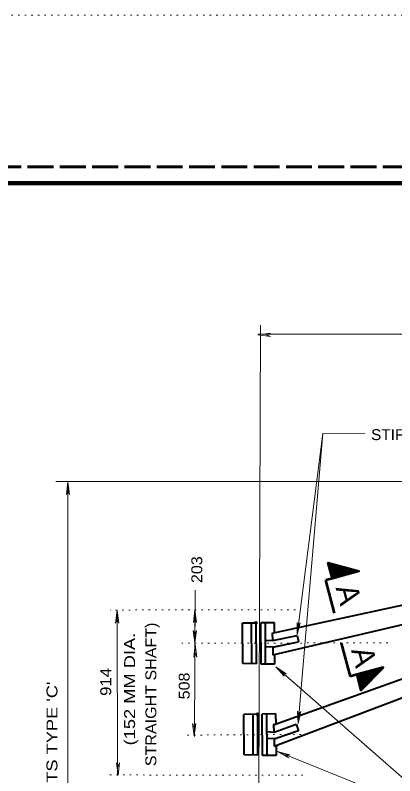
# Model space of a CAD drawing. Extents: x 312583 to 312854, y 144419 to 144597.
# Drawn here: x 312752.3 to 312778.8, y 144543.8 to 144596.8 of the extents above; entities that cross this region are included whole.
import ezdxf
from ezdxf.enums import TextEntityAlignment as Align

# ---------------------------------------------------------------- set-up
doc = ezdxf.new("R2010")
doc.units = 0
doc.header["$LTSCALE"] = 0.3
doc.header["$PDMODE"] = 32
doc.header["$PDSIZE"] = 0.15
doc.linetypes.add('DOTTED', pattern=[1.5, 0.3, -1.2])
doc.linetypes.add('LONG_DASHED', pattern=[7.5, 6, -1.5])
for name, color, linetype, lineweight in [('1', 7, 'Continuous', 35), ('2', 7, 'Continuous', 13), ('62', 7, 'DOTTED', 13), ('63', 7, 'LONG_DASHED', 60)]:
    doc.layers.add(name, color=color, linetype=linetype, lineweight=lineweight)

msp = doc.modelspace()

# ---------------------------------------------------------------- linework, layer by layer
at = {"layer": '1', "lineweight": 40}
for p, q in [((312770.2404, 144553.754), (312816.4474, 144563.7743)), ((312770.2864, 144552.259), (312811.2954, 144561.7963)), ((312770.3247, 144547.3676), (312809.233, 144561.3133)), ((312770.386, 144545.9033), (312809.325, 144560.608)), ((312769.1287, 144554.467), (312768.1704, 144554.4593)), ((312768.1857, 144551.638), (312768.1704, 144554.4593)), ((312768.822, 144551.6303), (312768.8067, 144554.467)), ((312769.144, 144551.6303), (312769.1287, 144554.467)), ((312770.4014, 144554.49), (312769.443, 144554.4746)), ((312769.4584, 144551.6073), (312769.443, 144554.4746)), ((312769.7804, 144551.6073), (312769.765, 144554.4823)), ((312770.409, 144553.7846), (312770.4014, 144554.49)), ((312770.2404, 144553.754), (312770.2557, 144553.2633)), ((312771.9807, 144553.6006), (312772.0727, 144553.156)), ((312769.7727, 144552.834), (312770.248, 144552.8186)), ((312770.271, 144552.788), (312772.0727, 144553.1636)), ((312770.271, 144552.811), (312770.2864, 144552.259)), ((312770.3554, 144552.811), (312772.0727, 144553.1636)), ((312770.409, 144552.282), (312770.409, 144551.5996)), ((312769.144, 144551.6303), (312768.1857, 144551.638)), ((312770.409, 144551.5996), (312769.4584, 144551.6073)), ((312769.2284, 144548.1113), (312768.27, 144548.1036)), ((312768.2854, 144545.2823), (312768.27, 144548.1036)), ((312768.9217, 144545.2746), (312768.9064, 144548.1113)), ((312769.2437, 144545.2746), (312769.2284, 144548.1113)), ((312770.501, 144548.1343), (312769.5427, 144548.119)), ((312769.558, 144545.2516), (312769.5427, 144548.119)), ((312769.88, 144545.2516), (312769.8647, 144548.1266)), ((312770.5087, 144547.429), (312770.501, 144548.1343)), ((312770.34, 144547.3983), (312770.6314, 144547.4596)), ((312770.34, 144547.3983), (312770.3554, 144546.8693)), ((312770.4397, 144546.417), (312772.065, 144546.992)), ((312771.9117, 144547.4213), (312772.0727, 144546.9613)), ((312769.8417, 144546.4553), (312770.4397, 144546.417)), ((312770.3707, 144546.394), (312770.386, 144545.9033)), ((312770.386, 144545.9033), (312770.6314, 144545.957)), ((312770.5087, 144545.9263), (312770.5087, 144545.244)), ((312769.2437, 144545.2746), (312768.2854, 144545.2823)), ((312770.5087, 144545.244), (312769.558, 144545.2516))]:
    msp.add_line(p, q, dxfattribs=at)
at = {"layer": '1'}
for p, q in [((312774.1427, 144558.6146), (312774.158, 144558.6376)), ((312774.158, 144558.5686), (312774.181, 144558.6376)), ((312774.1734, 144558.5226), (312774.1964, 144558.6223)), ((312774.181, 144558.4766), (312774.227, 144558.6146)), ((312774.1964, 144558.423), (312774.25, 144558.6146)), ((312774.204, 144558.3846), (312774.2654, 144558.5993)), ((312774.2194, 144558.3386), (312774.296, 144558.5993)), ((312774.2347, 144558.2926), (312774.319, 144558.5916)), ((312774.2424, 144558.2466), (312774.3344, 144558.5916)), ((312774.2577, 144558.2006), (312774.365, 144558.584)), ((312774.273, 144558.147), (312774.388, 144558.5763)), ((312774.2807, 144558.1086), (312774.411, 144558.5686)), ((312774.296, 144558.0626), (312774.434, 144558.5686)), ((312774.3114, 144558.009), (312774.457, 144558.561)), ((312774.319, 144557.963), (312774.48, 144558.5533)), ((312774.3344, 144557.9246), (312774.4954, 144558.5456)), ((312774.342, 144557.871), (312774.526, 144558.538)), ((312774.3574, 144557.825), (312774.549, 144558.538)), ((312774.3727, 144557.779), (312774.5644, 144558.5226)), ((312774.3804, 144557.733), (312774.595, 144558.515)), ((312774.3957, 144557.687), (312774.618, 144558.515)), ((312774.4034, 144557.6486), (312774.6334, 144558.4996)), ((312774.4187, 144557.595), (312774.664, 144558.4996)), ((312774.4417, 144557.5796), (312774.687, 144558.492)), ((312774.4724, 144557.5873), (312774.71, 144558.492)), ((312774.4954, 144557.595), (312774.733, 144558.4843)), ((312774.5184, 144557.595), (312774.756, 144558.4766)), ((312774.549, 144557.6026), (312774.779, 144558.469)), ((312774.572, 144557.618), (312774.802, 144558.469)), ((312774.6027, 144557.6256), (312774.825, 144558.4536)), ((312774.6257, 144557.6256), (312774.848, 144558.4536)), ((312774.6564, 144557.6333), (312774.871, 144558.446)), ((312774.687, 144557.641), (312774.894, 144558.4383)), ((312774.7024, 144557.6486), (312774.917, 144558.4383)), ((312774.733, 144557.6563), (312774.94, 144558.423)), ((312774.7637, 144557.664), (312774.9707, 144558.4153)), ((312774.7867, 144557.6716), (312774.986, 144558.4153)), ((312774.8174, 144557.687), (312775.009, 144558.4076)), ((312774.848, 144557.687), (312775.032, 144558.4)), ((312774.871, 144557.6946), (312775.055, 144558.3923)), ((312774.894, 144557.6946), (312775.078, 144558.3923)), ((312774.9247, 144557.7023), (312775.1087, 144558.3846)), ((312774.9477, 144557.71), (312775.124, 144558.377)), ((312774.9784, 144557.7176), (312775.147, 144558.3693)), ((312775.0014, 144557.7253), (312775.17, 144558.3693)), ((312775.032, 144557.733), (312775.193, 144558.354)), ((312775.055, 144557.7483), (312775.2237, 144558.3616)), ((312775.0857, 144557.7483), (312775.239, 144558.3463)), ((312775.1087, 144557.756), (312775.2697, 144558.3386)), ((312775.1394, 144557.7636), (312775.2927, 144558.3386)), ((312775.1624, 144557.7713), (312775.308, 144558.3233)), ((312775.1854, 144557.779), (312775.331, 144558.3233)), ((312775.216, 144557.7866), (312775.3617, 144558.3156)), ((312775.2467, 144557.7943), (312775.377, 144558.3156)), ((312775.2697, 144557.802), (312775.4, 144558.3003)), ((312775.3004, 144557.8096), (312775.4307, 144558.3003)), ((312775.331, 144557.8173), (312775.446, 144558.2926)), ((312775.354, 144557.8173), (312775.469, 144558.2926)), ((312775.3694, 144557.825), (312775.4997, 144558.2773)), ((312775.4, 144557.8326), (312775.5227, 144558.2773)), ((312775.4307, 144557.8403), (312775.538, 144558.2696)), ((312775.4614, 144557.848), (312775.5687, 144558.262)), ((312775.4844, 144557.8556), (312775.5917, 144558.262)), ((312775.515, 144557.8633), (312775.607, 144558.2466)), ((312775.538, 144557.871), (312775.6377, 144558.239)), ((312775.5687, 144557.8786), (312775.6607, 144558.239)), ((312775.584, 144557.8863), (312775.676, 144558.2236)), ((312775.6147, 144557.894), (312775.699, 144558.2236)), ((312775.6454, 144557.9016), (312775.7297, 144558.216)), ((312775.6684, 144557.9093), (312775.745, 144558.216)), ((312775.699, 144557.917), (312775.7757, 144558.2083)), ((312775.722, 144557.917), (312775.7987, 144558.2006)), ((312775.7527, 144557.9246), (312775.8217, 144558.193)), ((312775.7834, 144557.9323), (312775.8447, 144558.193)), ((312775.7987, 144557.94), (312775.8677, 144558.1776)), ((312775.8294, 144557.9476), (312775.8907, 144558.1776)), ((312775.8524, 144557.9553), (312775.9137, 144558.17)), ((312775.883, 144557.963), (312775.9367, 144558.1623)), ((312775.9137, 144557.9706), (312775.9597, 144558.1546)), ((312775.9444, 144557.9783), (312775.9827, 144558.147)), ((312775.9674, 144557.986), (312776.0057, 144558.1393)), ((312775.998, 144557.9936), (312776.0287, 144558.1393)), ((312776.0134, 144558.0013), (312776.0517, 144558.1316)), ((312776.0364, 144558.009), (312776.0747, 144558.124)), ((312776.067, 144558.0166), (312776.0977, 144558.1163)), ((312776.0977, 144558.0243), (312776.1207, 144558.1163)), ((312776.1284, 144558.032), (312776.1437, 144558.1086)), ((312776.1514, 144558.032), (312776.1667, 144558.101)), ((312776.182, 144558.0396), (312776.1897, 144558.0933)), ((312776.205, 144558.0473), (312776.2127, 144558.0933)), ((312776.228, 144558.055), (312776.2357, 144558.078)), ((312776.2587, 144558.0626), (312776.2587, 144558.078)), ((312777.1327, 144551.1473), (312777.4394, 144550.833)), ((312777.1634, 144551.155), (312777.4624, 144550.8483)), ((312777.1864, 144551.155), (312777.4777, 144550.8636)), ((312777.217, 144551.1703), (312777.493, 144550.8866)), ((312777.24, 144551.1703), (312777.5084, 144550.902)), ((312777.2707, 144551.178), (312777.5314, 144550.9173)), ((312777.286, 144551.1856), (312777.539, 144550.9326)), ((312777.3167, 144551.1933), (312777.562, 144550.948)), ((312777.3474, 144551.201), (312777.5774, 144550.971)), ((312777.3704, 144551.2086), (312777.5927, 144550.9786)), ((312777.401, 144551.2163), (312777.6157, 144551.0016)), ((312777.424, 144551.224), (312777.631, 144551.017)), ((312777.4547, 144551.2316), (312777.6464, 144551.04)), ((312777.4854, 144551.2393), (312777.6694, 144551.0476)), ((312777.5007, 144551.247), (312777.677, 144551.0706)), ((312777.5314, 144551.2546), (312777.7, 144551.0783)), ((312777.5544, 144551.2546), (312777.7154, 144551.1013)), ((312777.585, 144551.2623), (312777.7307, 144551.1243)), ((312777.6157, 144551.27), (312777.746, 144551.132)), ((312777.6464, 144551.2853), (312777.769, 144551.155)), ((312777.6694, 144551.2853), (312777.7767, 144551.1703)), ((312777.7, 144551.293), (312777.7997, 144551.1856)), ((312777.7154, 144551.3006), (312777.815, 144551.2086)), ((312777.7384, 144551.3083), (312777.838, 144551.224)), ((312777.769, 144551.316), (312777.8457, 144551.2393)), ((312777.7997, 144551.3236), (312777.8687, 144551.2546)), ((312777.8304, 144551.3313), (312777.884, 144551.2776)), ((312777.8534, 144551.339), (312777.8994, 144551.2853)), ((312777.884, 144551.3466), (312777.9147, 144551.3083)), ((312777.907, 144551.3543), (312777.9377, 144551.3236)), ((312777.93, 144551.362), (312777.9454, 144551.339)), ((312777.9607, 144551.3696), (312777.9684, 144551.3543)), ((312776.136, 144550.856), (312776.803, 144550.189)), ((312776.1437, 144550.879), (312776.8107, 144550.212)), ((312776.1437, 144550.8023), (312776.7724, 144550.1736)), ((312776.159, 144550.764), (312776.7647, 144550.1583)), ((312776.1667, 144550.7103), (312776.7417, 144550.143)), ((312776.1744, 144550.8866), (312776.8337, 144550.2196)), ((312776.182, 144550.6643), (312776.7264, 144550.12)), ((312776.1974, 144550.8943), (312776.849, 144550.2426)), ((312776.1974, 144550.626), (312776.711, 144550.1046)), ((312776.2204, 144550.902), (312776.8644, 144550.258)), ((312776.251, 144550.9096), (312776.8797, 144550.2733)), ((312776.274, 144550.9096), (312776.9027, 144550.2886)), ((312776.3047, 144550.9173), (312776.9104, 144550.3116)), ((312776.3277, 144550.925), (312776.9334, 144550.3193)), ((312776.3584, 144550.9403), (312776.9487, 144550.3423)), ((312776.389, 144550.948), (312776.964, 144550.3576)), ((312776.412, 144550.948), (312776.9794, 144550.373)), ((312776.435, 144550.9556), (312777.0024, 144550.396)), ((312776.4657, 144550.9633), (312777.0177, 144550.419)), ((312776.4887, 144550.971), (312777.033, 144550.4266)), ((312776.5194, 144550.971), (312777.0484, 144550.4496)), ((312776.55, 144550.9863), (312777.0714, 144550.465)), ((312776.573, 144550.994), (312777.079, 144550.4803)), ((312776.596, 144551.0016), (312777.102, 144550.4956)), ((312776.6267, 144551.0093), (312777.1174, 144550.511)), ((312776.6497, 144551.017), (312777.1327, 144550.5263)), ((312776.6804, 144551.0246), (312777.148, 144550.5493)), ((312776.7034, 144551.0323), (312777.171, 144550.557)), ((312776.734, 144551.04), (312777.1864, 144550.58)), ((312776.757, 144551.04), (312777.2094, 144550.5953)), ((312776.7877, 144551.0553), (312777.2247, 144550.6106)), ((312776.8107, 144551.0553), (312777.24, 144550.6336)), ((312776.8414, 144551.063), (312777.263, 144550.649)), ((312776.8644, 144551.0706), (312777.2707, 144550.6643)), ((312776.8874, 144551.0783), (312777.2937, 144550.6796)), ((312776.918, 144551.086), (312777.309, 144550.7026)), ((312776.9487, 144551.0936), (312777.3244, 144550.7103)), ((312776.9717, 144551.1013), (312777.3397, 144550.7333)), ((312777.0024, 144551.109), (312777.3627, 144550.7486)), ((312777.033, 144551.1166), (312777.3704, 144550.764)), ((312777.056, 144551.1243), (312777.3934, 144550.7793)), ((312777.0714, 144551.132), (312777.4087, 144550.7946)), ((312777.102, 144551.1396), (312777.4317, 144550.81)), ((312776.205, 144550.58), (312776.6957, 144550.0893)), ((312776.2204, 144550.5263), (312776.6727, 144550.0663)), ((312776.2357, 144550.4803), (312776.665, 144550.051)), ((312776.2434, 144550.4343), (312776.642, 144550.0356)), ((312776.2587, 144550.3883), (312776.6344, 144550.0203)), ((312776.2664, 144550.3423), (312776.6114, 144550.005)), ((312776.2817, 144550.2963), (312776.596, 144549.982)), ((312776.297, 144550.2426), (312776.5807, 144549.9743)), ((312776.3047, 144550.2043), (312776.5577, 144549.9513)), ((312776.32, 144550.1583), (312776.5424, 144549.936)), ((312776.3277, 144550.1123), (312776.527, 144549.9206)), ((312776.343, 144550.0586), (312776.504, 144549.9053)), ((312776.3584, 144550.0203), (312776.4964, 144549.89)), ((312776.366, 144549.9743), (312776.4734, 144549.8746)), ((312776.3814, 144549.9283), (312776.458, 144549.8516)), ((312776.3967, 144549.8746), (312776.4427, 144549.8363)), ((312776.4044, 144549.8286), (312776.4274, 144549.821))]:
    msp.add_line(p, q, dxfattribs=at)
at = {"layer": '1', "lineweight": 53}
for p, q in [((312774.4264, 144557.572), (312773.9664, 144557.4493)), ((312774.5874, 144555.1416), (312773.9664, 144557.4493)), ((312775.0474, 144553.064), (312775.6684, 144550.7486)), ((312776.1284, 144550.8713), (312775.6684, 144550.7486))]:
    msp.add_line(p, q, dxfattribs=at)
at = {"layer": '1', "lineweight": 158}
msp.add_lwpolyline([(312616.5, 144423.1446), (312616.5, 144585.0846), (312849, 144585.0846)], dxfattribs=at)
at = {"layer": '1', "lineweight": 53}
for points in [[(312774.4264, 144557.572), (312774.135, 144558.6453), (312776.274, 144558.0703)], [(312776.1284, 144550.8713), (312776.412, 144549.798), (312777.976, 144551.3696)]]:
    msp.add_lwpolyline(points, close=True, dxfattribs=at)
at = {"layer": '1', "lineweight": 40}
for points in [[(312769.788, 144553.2633), (312770.2634, 144553.248), (312771.9807, 144553.6006)], [(312769.8724, 144546.9076), (312770.3707, 144546.877), (312771.9117, 144547.4213)]]:
    msp.add_lwpolyline(points, dxfattribs=at)
at = {"layer": '1'}
for p in [(312769.1134, 144554.4746), (312769.213, 144548.119)]:
    msp.add_point(p, dxfattribs=at)
at = {"layer": '2'}
for p, q in [((312769.3127, 144541.1116), (312769.4277, 144575.1976)), ((312769.2437, 144574.5306), (312770.11, 144574.638)), ((312769.2437, 144574.5306), (312770.11, 144574.4233)), ((312828.5454, 144574.5996), (312769.2667, 144574.5843)), ((312770.11, 144574.638), (312769.834, 144574.5306)), ((312770.11, 144574.4233), (312769.834, 144574.5306)), ((312773.7747, 144567.669), (312771.973, 144553.639)), ((312773.7747, 144567.669), (312772.042, 144547.4596)), ((312776.6957, 144567.692), (312773.7747, 144567.669)), ((312840.996, 144564.3416), (312755.1677, 144564.311)), ((312756.0034, 144564.2803), (312755.9037, 144563.414)), ((312755.9957, 144517.6746), (312756.0034, 144564.265)), ((312756.0034, 144564.2803), (312756.1184, 144563.414)), ((312755.9037, 144563.414), (312756.0034, 144563.69)), ((312756.1184, 144563.414), (312756.0034, 144563.69)), ((312764.8277, 144546.5703), (312764.866, 144556.7516)), ((312759.4304, 144555.3333), (312759.3307, 144554.467)), ((312759.4534, 144543.8486), (312759.4304, 144555.3486)), ((312759.4304, 144555.3333), (312759.5454, 144554.467)), ((312764.8584, 144555.3793), (312764.751, 144554.513)), ((312764.8507, 144553.0793), (312764.8584, 144555.3793)), ((312764.8584, 144555.3793), (312764.9657, 144554.5053)), ((312759.3307, 144554.467), (312759.438, 144554.743)), ((312759.5454, 144554.467), (312759.438, 144554.743)), ((312764.751, 144554.513), (312764.8584, 144554.789)), ((312764.9657, 144554.5053), (312764.8584, 144554.789)), ((312771.973, 144553.639), (312771.9807, 144554.513)), ((312771.973, 144553.639), (312771.9807, 144554.513)), ((312771.973, 144553.639), (312772.1954, 144554.4823)), ((312771.973, 144553.639), (312772.1954, 144554.4823)), ((312771.9807, 144554.513), (312772.0497, 144554.2216)), ((312771.9807, 144554.513), (312772.0497, 144554.2216)), ((312772.1954, 144554.4823), (312772.0497, 144554.2216)), ((312772.1954, 144554.4823), (312772.0497, 144554.2216)), ((312764.7434, 144553.9456), (312764.8507, 144553.6696)), ((312764.8507, 144553.0793), (312764.7434, 144553.9456)), ((312764.958, 144553.9456), (312764.8507, 144553.6696)), ((312764.8507, 144553.0793), (312764.958, 144553.9456)), ((312764.8737, 144552.9643), (312764.774, 144552.098)), ((312764.8737, 144552.9643), (312764.9887, 144552.098)), ((312764.774, 144552.098), (312764.8737, 144552.374)), ((312764.9887, 144552.098), (312764.8737, 144552.374)), ((312782.8444, 144540.598), (312770.4857, 144551.4233)), ((312770.4857, 144551.4233), (312771.0607, 144550.7716)), ((312770.4857, 144551.4233), (312771.2064, 144550.9326)), ((312770.4857, 144551.4233), (312771.0607, 144550.7716)), ((312770.4857, 144551.4233), (312771.2064, 144550.9326)), ((312771.0607, 144550.7716), (312770.9227, 144551.0323)), ((312771.2064, 144550.9326), (312770.9227, 144551.0323)), ((312771.0607, 144550.7716), (312770.9227, 144551.0323)), ((312771.2064, 144550.9326), (312770.9227, 144551.0323)), ((312772.0114, 144548.3336), (312772.0957, 144548.0423)), ((312772.042, 144547.4596), (312772.0114, 144548.3336)), ((312772.042, 144547.4596), (312772.226, 144548.3106)), ((312772.226, 144548.3106), (312772.0957, 144548.0423)), ((312764.6974, 144547.4673), (312764.8047, 144547.199)), ((312764.8047, 144546.6086), (312764.6974, 144547.4673)), ((312764.912, 144547.475), (312764.8047, 144547.199)), ((312764.8047, 144546.6086), (312764.912, 144547.475)), ((312782.8444, 144540.598), (312770.616, 144545.5123)), ((312770.616, 144545.5123), (312771.3827, 144545.0906)), ((312770.616, 144545.5123), (312771.4594, 144545.29)), ((312771.3827, 144545.0906), (312771.168, 144545.29)), ((312771.4594, 144545.29), (312771.168, 144545.29)), ((312759.3844, 144544.7303), (312759.4917, 144544.4543)), ((312759.4994, 144543.864), (312759.3844, 144544.7303)), ((312759.599, 144544.7303), (312759.4917, 144544.4543)), ((312759.4994, 144543.864), (312759.599, 144544.7303))]:
    msp.add_line(p, q, dxfattribs=at)
at = {"layer": '2', "linetype": 'DOTTED'}
for p, q in [((312771.8504, 144555.3793), (312758.955, 144555.3716)), ((312778.2827, 144553.087), (312763.9537, 144553.0563)), ((312772.249, 144546.7083), (312764.1377, 144546.6623)), ((312772.3794, 144543.8716), (312758.9397, 144543.887))]:
    msp.add_line(p, q, dxfattribs=at)
at = {"layer": '62'}
msp.add_line((312601.2, 144596.7846), (312853.5, 144596.7846), dxfattribs=at)
at = {"layer": '63'}
msp.add_line((312851.75, 144586.2246), (312583.526, 144586.2246), dxfattribs=at)

# ---------------------------------------------------------------- texts
at = {"layer": '1'}
for rotation, p in [(284.986, (312774.822, 144556.2596)), (285.004, (312775.8956, 144551.9202))]:
    msp.add_text('A', height=1.533, rotation=rotation, dxfattribs=at).set_placement(p, align=Align.CENTER)
at = {"layer": '2', "width": 1.05}
msp.add_text('STIFFENERS', height=0.76, dxfattribs=at).set_placement((312777.1268, 144567.2013))
at = {"layer": '2'}
for s, width, p in [('203', 1.1, (312765.3647, 144557.248)), ('STRAIGHT SHAFT)', 1.1, (312762.1666, 144544.4994)), ('(152 MM DIA. ', 1.25, (312760.6862, 144545.9483)), ('914 ', 1.15, (312759.0236, 144549.3907)), ('508', 1.1, (312764.4858, 144549.1522)), ("7.874 M FOR LIGHTS TYPE 'C'", 1.25, (312755.2773, 144532.3998))]:
    msp.add_text(s, height=0.76, rotation=90, dxfattribs=dict(at, width=width)).set_placement(p)

doc.saveas('drawing.dxf')
